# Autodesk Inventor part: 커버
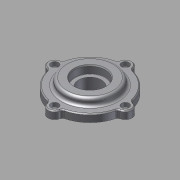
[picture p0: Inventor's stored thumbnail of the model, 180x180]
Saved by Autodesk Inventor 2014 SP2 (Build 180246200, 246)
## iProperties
Company: 한국ATC센터
Created: 2015-12
Part Number: 커버
Document SubType Name: Modeling
Designer: mdu
Density: 1 g/cm^3
Material: 일반
Appearance: 기본값
Author: mdu
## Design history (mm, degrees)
sketch "스케치1"
  geometry: C1 r 1.621 at (0, 6.75) reference; C2 r 1.621 at (-37, -30.25) reference; C3 r 1.621 at (0, -67.25) reference; C4 r 1.621 at (37, -30.25) reference; C5 r 10 at (0, -30.25) reference; C6 r 12 at (0, -30.25); C7 r 24.5 at (0, -30.25) reference; A1 r 3 centre (-38.77, -20.408) between (-38.239, -23.361) and (-35.862, -21.146) reference; A2 r 7 centre (-37, -30.25) between (-38.239, -23.361) and (-38.239, -37.139) reference; A3 r 3 centre (-38.77, -40.092) between (-35.862, -39.354) and (-38.239, -37.139) reference; A4 r 37 centre (0, -30.25) between (-35.862, -39.354) and (-9.104, -66.113) reference; A5 r 3 centre (-9.842, -69.02) between (-6.889, -68.489) and (-9.104, -66.113) reference; A6 r 7 centre (0, -67.25) between (-6.889, -68.489) and (6.889, -68.489) reference; A7 r 3 centre (9.842, -69.02) between (9.104, -66.112) and (6.889, -68.489) reference; A8 r 37 centre (0, -30.25) between (9.104, -66.112) and (35.863, -39.354) reference; A9 r 3 centre (38.77, -40.092) between (38.239, -37.139) and (35.863, -39.354) reference; A10 r 7 centre (37, -30.25) between (38.239, -37.139) and (38.239, -23.361) reference; A11 r 3 centre (38.77, -20.408) between (35.863, -21.146) and (38.239, -23.361) reference; A12 r 37 centre (0, -30.25) between (35.863, -21.146) and (9.104, 5.612) reference; A13 r 3 centre (9.842, 8.52) between (6.889, 7.989) and (9.104, 5.612) reference; A14 r 7 centre (0, 6.75) between (6.889, 7.989) and (-6.889, 7.989) reference; A15 r 3 centre (-9.842, 8.52) between (-9.104, 5.612) and (-6.889, 7.989) reference; A16 r 37 centre (0, -30.25) between (-9.104, 5.612) and (-35.862, -21.146) reference; 1 further point
  constraints: 1 centre point, 1 coincident
  dimensions: "d2" = 2 radial gap between concentric circles of C6 C5
extrude "돌출1" new body sketch "스케치1" distance "d0" = 8; taper "d1" = 0 deg
sketch "스케치2"
  geometry: C1 r 23.5 at (0, -30.25) reference; C2 r 12 at (0, -30.25) reference; 1 further point
extrude "돌출2" join sketch "스케치2" distance "d4" = 5; taper "d5" = 0 deg
sketch "스케치3"
  geometry: C1 r 23.5 at (0, 0) reference; C2 r 20.5 at (0, 0); 1 further point
  constraints: 1 centre point
  dimensions: "d6" = 3 radial gap between concentric circles of C2 C1
node "작업 평면1"
extrude "돌출3" join sketch "스케치3" stored distance "d7" = 5; taper "d8" = 0 deg
fillet "모깎기1" dims "d9" = 3
sketch "스케치4"
  geometry: C1 r 12 at (0, -30.25) reference; C2 r 27 at (0, -30.25); 1 further point
  constraints: 1 centre point
  dimensions: "d10" = 15 radial gap between concentric circles of C1 C2
extrude "돌출4" join sketch "스케치4" distance "d11" = 7; taper "d12" = 0 deg
fillet "모깎기2" dims "d13" = 3
chamfer "모따기1" distance "d14" = 1; stored, may be unused: second distance "d15" = 2, angle "d16" = 45 deg
node "작업점1"
  node "작업축1"
chamfer "모따기2" distance "d24" = 1; stored, may be unused: second distance "d25" = 2, angle "d26" = 45 deg
hole "구멍6" diameter "d43" = 4.5; stored, may be unused: countersink angle "d47" = 90 deg, drill point angle "d49" = 118 deg; dims "d41" = 10, "d42" = 10, "d44" = 6, "d45" = 8, "d46" = 4.4, "d48" = 8
sketch "스케치8"
  geometry: C1 r 12 at (0, 0) reference; C2 r 16 at (0, 0); 1 further point
  constraints: 1 centre point, 1 coincident
  dimensions: "d53" = 32 diameter of C2
extrude "돌출5" cut sketch "스케치8" distance "d54" = 8.3; taper "d55" = 0 deg
fillet "모깎기3" dims "d56" = 0.3
chamfer "모따기3" distance "d57" = 1.2; stored, may be unused: second distance "d58" = 2, angle "d59" = 30 deg
node "솔리드1"
pattern_circular "원형 패턴1" dims angle "d51" = 360 deg
node "참조1"
node "참조2"
